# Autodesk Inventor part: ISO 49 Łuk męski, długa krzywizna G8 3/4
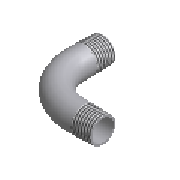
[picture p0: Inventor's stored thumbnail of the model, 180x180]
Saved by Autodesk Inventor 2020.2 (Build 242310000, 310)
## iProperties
Manager: www.cadconsulting.pl
Company: Fabian Stasiak CAD Consulting
Created: 2014-02
Part Number: ISO 49 Łuk męski, długa krzywizna G8 3/4
Material: Żelazo, ciągliwe
Description: Elementy z żeliwa ciągliwego - Łuki męskie z długą krzywizną G8
Document SubType Name: Modeling
Standard: ISO 49
Designer: F.Stasiak
Standard Revision: Second edition 1994-12-15
Standards Organization: ISO
Language: pl-PL
Size Designation: 3/4
Categories: <MemberInstance><Categories><Category DisplayName="Rury cienko- i grubościenne" InternalName="4347fa0f-2144-441d-94cd-e3e15c92b736" Mnemonic="TUBEANDPIPE"><Cate
Density: 7.15 g/cm^3
Appearance: Częściowo polerowana
Catalog Web Link: www.expertbooks.pl
NAME: PIPING: ISO 49 Male Long Sweep Bend G8
DATA: <meta><inlinegroups number="0" deflen="0"></inlinegroups><connections number="2"></connections><angles><a>1.57079632679489</a></angles></meta>
IsCustomPart: 0
Author: F.Stasiak
Subject: Zbiór ćwiczeń. Autodesk Inventor 2020. Kurs Professional
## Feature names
1. Revolution1
2. Revolution2
3. Sweep1
## Parameters: MD = 24.117 mm, d26 = 90 deg, d0 = 23.20887 mm, d37 = 90 deg, D = 27.2 mm, B = 14.53 mm, d2 = 0.3124 mm, d3 = 21.795 mm, d4 = 14.53 mm, d5 = 0.3124 mm, d6 = 14.53 mm, d7 = 21.795 mm, d9 = 23.20887 mm, d11 = 27.2 mm, d12 = 0, d112 = 0, d114 = 0, DD = 26.441 mm, A = 9.53 mm, L2 = 14.53 mm, d116 = 9.53 mm, d117 = 26.441 mm, d118 = 9.53 mm, d119 = 26.441 mm, d120 = 0, Size_Designation = 7.5 mm
